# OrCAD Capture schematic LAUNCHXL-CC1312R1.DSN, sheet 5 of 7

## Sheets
5 4_XDS110: size A3
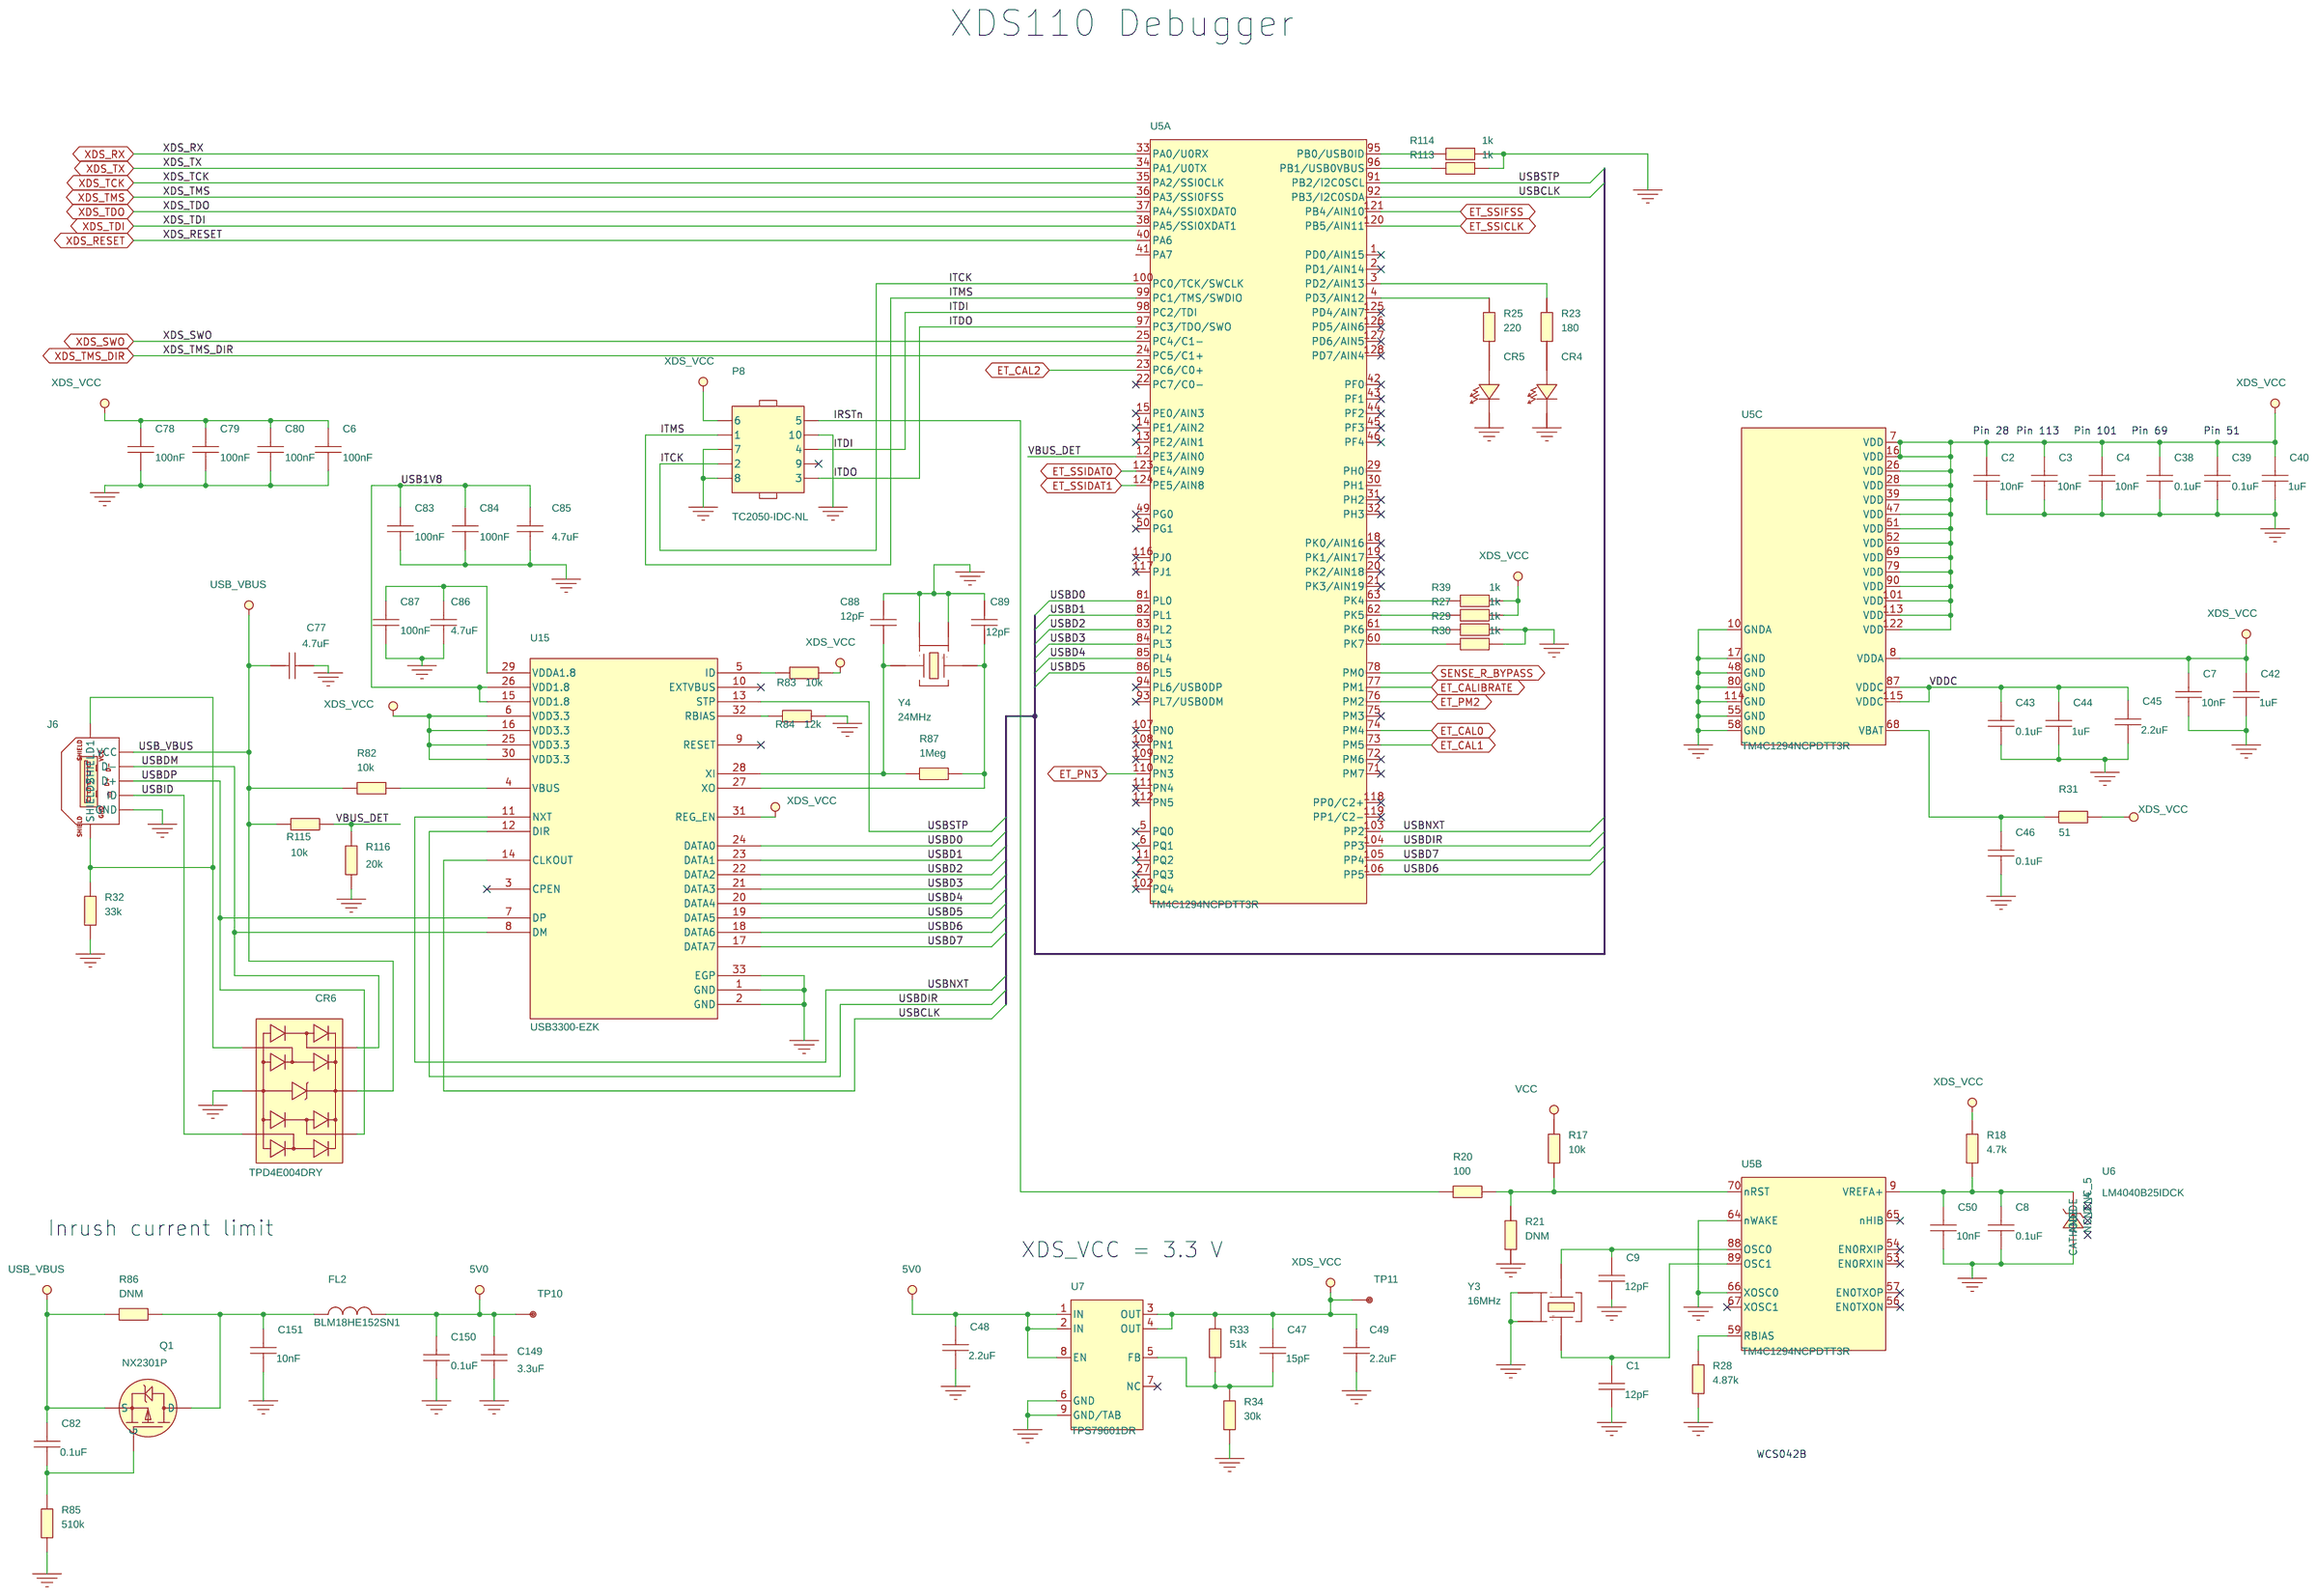
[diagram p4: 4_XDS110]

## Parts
C1  12pF  [CAPC1005X60B2N]
C2  10nF  [CAPC1005X60B2N]
C3  10nF  [CAPC1005X60B2N]
C4  10nF  [CAPC1005X60B2N]
C6  100nF  [CAPC0603X35A2N]
C7  10nF  [CAPC1005X60B2N]
C8  0.1uF  [CAPC1005X60B2N]
C9  12pF  [CAPC1005X60B2N]
C38  0.1uF  [CAPC1005X60B2N]
C39  0.1uF  [CAPC1005X60B2N]
C40  1uF  [CAPC1005X60B2N]
C42  1uF  [CAPC1005X60B2N]
C43  0.1uF  [CAPC1005X60B2N]
C44  1uF  [CAPC1005X60B2N]
C45  2.2uF  [CAPC1005X60B2N]
C46  0.1uF  [CAPC1005X60B2N]
C47  15pF  [CAPC1005X60B2N]
C48  2.2uF  [CAPC1005X60B2N]
C49  2.2uF  [CAPC1005X60B2N]
C50  10nF  [CAPC1005X60B2N]
C77  4.7uF  [CAPC2012X150A2N]
C78  100nF  [CAPC0603X35A2N]
C79  100nF  [CAPC0603X35A2N]
C80  100nF  [CAPC0603X35A2N]
C82  0.1uF  [CAPC1005X60B2N]
C83  100nF  [CAPC0603X35N]
C84  100nF  [CAPC0603X35N]
C85  4.7uF  [CAPC1005X60B2N]
C86  4.7uF  [CAPC1005X60B2N]
C87  100nF  [CAPC0603X35N]
C88  12pF  [CAPC1005X60B2N]
C89  12pF  [CAPC1005X60B2N]
C149  3.3uF  [CAPC1608X90A2N]
C150  0.1uF  [CAPC1005X60B2N]
C151  10nF  [CAPC1005X60B2N]
CR4  LS L296-P2Q2-1  [LEDC1708X67L]
CR5  LPL296-J2L2-25  [LEDC1707X65L]
CR6  TPD4E004DRY  [SON50P100X145X60-6N]
FL2  BLM18HE152SN1  [FIL_BLM18HE152SN1DL]
J6  105164-0001  [MOLEX_1051640001_A2N]
P8  TC2050-IDC-NL  [TAGCONNECT_TC2050IDCNL_A2N]
Q1  NX2301P  [SOT95P230X110-3N]
R17  10k  [RESC1005X40B2N]
R18  4.7k  [RESC1005X40B2N]
R20  100  [RESC1005X40B2N]
R21  DNM  [RESC1005X40B2N]
R23  180  [RESC1005X40B2N]
R25  220  [RESC1005X40B2N]
R27  1k  [RESC1005X40B2N]
R28  4.87k  [RESC1005X40B2N]
R29  1k  [RESC1005X40B2N]
R30  1k  [RESC1005X40B2N]
R31  51  [RESC1005X40B2N]
R32  33k  [RESC1005X40B2N]
R33  51k  [RESC1005X40B2N]
R34  30k  [RESC1005X40B2N]
R39  1k  [RESC1005X40B2N]
R82  10k  [RESC0603X35N]
R83  10k  [RESC0603X35N]
R84  12k  [RESC0603X35N]
R85  510k  [RESC1005X40N]
R86  DNM  [RESC1005X40B2N]
R87  1Meg  [RESC1005X40B2N]
R113  1k  [RESC0603X35N]
R114  1k  [RESC0603X35N]
R115  10k  [RESC0603X35N]
R116  20k  [RESC0603X35N]
TP10  HOLE_0.6mm_PTH  [MTG60_120]
TP11  HOLE_0.6mm_PTH  [MTG60_120]
U5  TM4C1294NCPDTT3R  [QFP40P1600X1600X120-128N]  (sections A,B,C)
U6  LM4040B25IDCK  [SOT65P210X110-5N]
U7  TPS79601DR  [SON65P300X300X100-9AL]
U15  USB3300-EZK  [QFNWB50P500X500X100-33N]
Y3  16MHz  [OSCCC250X320X100-4BN]
Y4  24MHz  [OSCCC250X320X70-4AN]

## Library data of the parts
C1 C9 C88 C89 = CAPACITOR: CAPACITOR, CERAMIC C0G/NP0, 12pF, 50V, -5%/+5%, -55DEGC/+125DEGC, 0402, SMD; AutoDoc File: https://notefied-dynamic-precision.com/DB/Apps/Desktop/Item/Object.aspx?id=113345; BU Name: TEXAS INSTRUMENTS NORWAY; Budget Currency: EUR; Budget Price: 0.007; Country of Origin: PHILIPPINES; Datasheet URL 1: http://psearch.murata.com/capacitor/product/GRM1555C1H120JA01%23.pdf; Datasheet URL 2: http://search.murata.co.jp/Ceramy/image/img/w_hinm/L0005E.pdf; Definied Quality: INDUSTRIAL; Dielectric Type: C0G/NP0; Esd Level: N/A; Last Time Buy: N/A; Lead Time: 12; LifeCycle Status: ACTIVE; MPN: CAPACITOR_0402_12pF_C0G/NP0_M_+/-5%_50V; MPN Status: ACTIVE; MSL: N/A; MTBF: N/A; MTBF Standard: N/A; Manufacturer: MANUFACTURER SELECTION; Max Oper Temp: +125DEGC; Max Tol: +5%; Min Oper Temp: -55DEGC; Min Tol: -5%; Mounting Type: SMD; NOTE Status: PREFERRED; Old Footprint: CAPC1005X60N; PCB Package: 0402; Packing Size: 10000; Packing Type: TAPE_&_REEL; Part Number: 02-07617; Part Type: CAPACITOR\CERAMIC\0402\STANDARD; REACH/SVHC_COMPLIANCE: COMPLIANT; REACH/SVHC_DETAILS: SVHC LIST VERSION Dec 17, 2015; REACH/SVHC_SOURCE: REACH DECLARATION; REACH/SVHC_STATUS: UNAFFECTED; Revision: R000; RoHS Status: ROHS_COMPLIANT; Rtd Voltage: 50V; Vendor: MURATA; Vendor Part Number: GRM1555C1H120JA01D; Vendor Part Status: ACTIVE; WEIGHT: 0.0016g
C2-C4 C7 C50 C151 = CAPACITOR: CAPACITOR, CERAMIC X7R, 10nF, 25V, -10%/+10%, -55DEGC/+125DEGC, 0402, SMD; AutoDoc File: https://notefied-dynamic-precision.com/DB/Apps/Desktop/Item/Object.aspx?id=114570; BU Name: TEXAS INSTRUMENTS NORWAY; Budget Currency: EUR; Budget Price: 0.003; Client Status: UNDER_REVIEW; Country of Origin: JAPAN,CHINA; Datasheet URL 1: http://psearch.murata.com/capacitor/product/GRM155R71E103KA01%23.pdf; Datasheet URL 2: http://search.murata.co.jp/Ceramy/image/img/w_hinm/L0005E.pdf; Definied Quality: INDUSTRIAL; Dielectric Type: X7R; Esd Level: N/A; Last Time Buy: N/A; Lead Time: 18; LifeCycle Status: ACTIVE; MPN: CAPACITOR_0402_10nF_X7R_M_+/-10%_25V; MPN Status: ACTIVE; MSL: N/A; MTBF: N/A; MTBF Standard: N/A; Manufacturer: MANUFACTURER SELECTION; Max Oper Temp: +125DEGC; Max Tol: +10%; Min Oper Temp: -55DEGC; Min Tol: -10%; Mounting Type: SMD; NOTE Status: PREFERRED; Old Footprint: CAPC1005X60N; PCB Package: 0402; Packing Size: 10000; Packing Type: TAPE_&_REEL; Part Number: 02-07775; Part Type: CAPACITOR\CERAMIC\0402\STANDARD; REACH/SVHC_COMPLIANCE: COMPLIANT; REACH/SVHC_DETAILS: SVHC LIST VERSION Dec 17, 2015; REACH/SVHC_SOURCE: MATERIAL DECLARATION; REACH/SVHC_STATUS: UNAFFECTED; Revision: R000; RoHS Status: ROHS_COMPLIANT; Rtd Voltage: 25V; Vendor: MURATA; Vendor Part Number: GRM155R71E103KA01D; Vendor Part Status: ACTIVE; WEIGHT: 0.0016g
C6 C78-C80 = CAPACITOR: CAPACITOR, CERAMIC X5R, 100nF, 10V, -10%/+10%, -55DEGC/+85DEGC, 0201, SMD; ALT_SYMBOLS: CAPC0603X35A2L,CAPC0603X35A2M; AutoDoc File: https://notefied-dynamic-precision.com/DB/Apps/Desktop/Item/Object.aspx?id=96679; BU Name: DYNAMIC PRECISION GDANSK; Budget Currency: EUR; Budget Price: 0.008; Client Status: UNDER_REVIEW; Country of Origin: MISSING INFO; Datasheet URL 1: http://psearch.murata.com/capacitor/product/GRM033R61A104KE84%23.pdf; Datasheet URL 2: http://search.murata.co.jp/Ceramy/image/img/w_hinm/L0005E.pdf; Dielectric Type: X5R; Last Time Buy: N/A; Lead Time: 17; LifeCycle Status: ACTIVE; MPN: GRM155R70J104KA01D; MPN Status: ACTIVE; Manufacturer: MURATA; Max Oper Temp: +85DEGC; Max Tol: +10%; Min Oper Temp: -55DEGC; Min Tol: -10%; Mounting Type: SMD; NOTE Status: PREFERRED; Old Footprint: CAPC1005X60N,0402; PCB Package: 0201; Packing Size: 15000; Packing Type: TAPE_&_REEL; Part Number: 02-06085; Part Type: CAPACITOR\CERAMIC\0201\STANDARD; REACH/SVHC_COMPLIANCE: COMPLIANT; REACH/SVHC_DETAILS: SVHC LIST VERSION Jun 20, 2016; REACH/SVHC_SOURCE: REACH DECLARATION; REACH/SVHC_STATUS: UNAFFECTED; Revision: R004; RoHS Status: ROHS_COMPLIANT; Rtd Voltage: 10V; Vendor: MURATA; Vendor Part Number: GRM033R61A104KE84D; Vendor Part Status: ACTIVE; WEIGHT: 0.00033g
C8 C38 C39 C43 C46 C150 = CAPACITOR: CAPACITOR, CERAMIC X7R, 0.1uF, 25V, -10%/+10%, -55DEGC/+125DEGC, 0402, SMD; AutoDoc File: https://notefied-dynamic-precision.com/DB/Apps/Desktop/Item/Object.aspx?id=115293; BU Name: TEXAS INSTRUMENTS NORWAY; Client Status: UNDER_REVIEW; Datasheet URL 1: http://psearch.en.murata.com/capacitor/product/GRM155R71E104KE14%23.pdf; Datasheet URL 2: http://search.murata.co.jp/Ceramy/image/img/w_hinm/L0005E.pdf; Dielectric Type: X7R; Last Time Buy: N/A; LifeCycle Status: ACTIVE; MPN: GRM155R70J104KA01D; MPN Status: ACTIVE; Manufacturer: MURATA; Max Oper Temp: +125DEGC; Max Tol: +10%; Min Oper Temp: -55DEGC; Min Tol: -10%; Mounting Type: SMD; NOTE Status: PREFERRED; Old Footprint: CAPC1005X60N,0402; PCB Package: 0402; Packing Size: 10000; Packing Type: TAPE_&_REEL; Part Number: 02-07861; Part Type: CAPACITOR\CERAMIC\0402\STANDARD; REACH/SVHC_COMPLIANCE: COMPLIANT; REACH/SVHC_DETAILS: SVHC LIST VERSION Jun 20, 2016; REACH/SVHC_SOURCE: REACH DECLARATION; REACH/SVHC_STATUS: UNAFFECTED; Revision: R002; RoHS Status: ROHS_COMPLIANT; Rtd Voltage: 25V; Vendor: MURATA; Vendor Part Number: GRM155R71E104KE14D; Vendor Part Status: ACTIVE; WEIGHT: 0.0016g
C40 C42 C44 = CAPACITOR: CAPACITOR, CERAMIC X5R, 1uF, 16V, -10%/+10%, -55DEGC/+85DEGC, 0402, SMD; AutoDoc File: https://notefied-dynamic-precision.com/DB/Apps/Desktop/Item/Object.aspx?id=115295; BU Name: TEXAS INSTRUMENTS NORWAY; Client Status: UNDER_REVIEW; Datasheet URL 1: http://psearch.en.murata.com/capacitor/product/GRM155R61C105KA12%23.pdf; Datasheet URL 2: http://search.murata.co.jp/Ceramy/image/img/w_hinm/L0005E.pdf; Definied Quality: INDUSTRIAL; Dielectric Type: X5R; Esd Level: N/A; Last Time Buy: N/A; MPN: GRM155R61A105KE15D; MPN Status: ACTIVE; MSL: 1; MTBF: N/A; MTBF Standard: N/A; Manufacturer: MURATA; Max Oper Temp: +85DEGC; Max Tol: +10%; Min Oper Temp: -55DEGC; Min Tol: -10%; Mounting Type: SMD; NOTE Status: PREFERRED; Old Footprint: CAPC1005X60N,0402; PCB Package: 0402; Packing Size: 10000; Packing Type: TAPE_&_REEL; Part Number: 02-07863; Part Type: CAPACITOR\CERAMIC\0402\STANDARD; REACH/SVHC_COMPLIANCE: COMPLIANT; REACH/SVHC_DETAILS: SVHC LIST VERSION Jun 20, 2016; REACH/SVHC_SOURCE: REACH DECLARATION; REACH/SVHC_STATUS: UNAFFECTED; Revision: R002; RoHS Status: ROHS_COMPLIANT; Rtd Voltage: 16V; Vendor: MURATA; Vendor Part Number: GRM155R61C105KA12D; Vendor Part Status: ACTIVE; WEIGHT: 0.0016g
C45 C48 C49 = CAPACITOR: CAPACITOR, CERAMIC X5R, 2.2uF, 6.3V, -10%/+10%, -55DEGC/+85DEGC, 0402, SMD; AutoDoc File: https://notefied-dynamic-precision.com/DB/Apps/Desktop/Item/Object.aspx?id=113352; BU Name: TEXAS INSTRUMENTS NORWAY; Budget Currency: USD; Budget Price: 0.0126; Country of Origin: PHILIPPINES; Datasheet URL 1: http://psearch.murata.com/capacitor/product/GRM155R60J225KE95%23.pdf; Datasheet URL 2: http://psearch.en.murata.com/capacitor/product/GRM155R60J225KE95%23.html; Dielectric Type: X5R; Last Time Buy: N/A; Lead Time: N/A; Max Oper Temp: +85DEGC; Max Tol: +10%; Min Oper Temp: -55DEGC; Min Tol: -10%; Mounting Type: SMD; PCB Package: 0402; Packing Size: 10000; Packing Type: TAPE_&_REEL; Part Number: 02-07624; Part Type: CAPACITOR\CERAMIC\0402\STANDARD; Revision: R000; RoHS Status: ROHS_COMPLIANT; Rtd Voltage: 6.3V; Vendor: MURATA; Vendor Part Number: GRM155R60J225KE95D; Vendor Part Status: NRND; Weight: 0.0016g
C47 = CAPACITOR: CAPACITOR, CERAMIC C0G/NP0, 15pF, 50V, -5%/+5%, -55DEGC/+125DEGC, 0402, SMD; AutoDoc File: https://notefied-dynamic-precision.com/DB/Apps/Desktop/Item/Object.aspx?id=114571; BU Name: TEXAS INSTRUMENTS NORWAY; Budget Currency: EUR; Budget Price: 0.006; Client Status: UNDER_REVIEW; Country of Origin: PHILIPPINES; Datasheet URL 1: http://psearch.murata.com/capacitor/product/GRM1555C1H150JA01%23.pdf; Datasheet URL 2: http://search.murata.co.jp/Ceramy/image/img/w_hinm/L0005E.pdf; Definied Quality: INDUSTRIAL; Dielectric Type: C0G/NP0; Esd Level: N/A; Last Time Buy: N/A; Lead Time: 12; LifeCycle Status: ACTIVE; MPN: CAPACITOR_0402_15pF_C0G/NP0_M_+/-5%_50V; MPN Status: ACTIVE; MSL: N/A; MTBF: N/A; MTBF Standard: N/A; Manufacturer: MANUFACTURER SELECTION; Max Oper Temp: +125DEGC; Max Tol: +5%; Min Oper Temp: -55DEGC; Min Tol: -5%; Mounting Type: SMD; NOTE Status: PREFERRED; Old Footprint: CAPC1005X60N; PCB Package: 0402; Packing Size: 10000; Packing Type: TAPE_&_REEL; Part Number: 02-07776; Part Type: CAPACITOR\CERAMIC\0402\STANDARD; REACH/SVHC_COMPLIANCE: COMPLIANT; REACH/SVHC_DETAILS: SVHC LIST VERSION Dec 17, 2015; REACH/SVHC_SOURCE: REACH DECLARATION; REACH/SVHC_STATUS: UNAFFECTED; Revision: R000; RoHS Status: ROHS_COMPLIANT; Rtd Voltage: 50V; Vendor: MURATA; Vendor Part Number: GRM1555C1H150JA01D; Vendor Part Status: ACTIVE; WEIGHT: 0.0016g
C77 = CAPACITOR: CAPACITOR, CERAMIC X7R, 4.7uF, 25V, -10%/+10%, -55DEGC/+125DEGC, 0805, SMD; ALT_SYMBOLS: CAPC2012X150A2L,CAPC2012X150A2M; AutoDoc File: https://notefied-dynamic-precision.com/DB/Apps/Desktop/Item/Object.aspx?id=100426; BU Name: DYNAMIC PRECISION GDANSK; Budget Currency: EUR; Budget Price: 0.165; Client Status: UNDER_REVIEW; Country of Origin: JAPAN,CHINA; Datasheet URL 1: http://product.tdk.com/info/en/documents/chara_sheet/C2012X7R1E475K125AB.pdf; Datasheet URL 2: http://product.tdk.com/info/en/catalog/datasheets/mlcc_commercial_general_en.pdf; Dielectric Type: X7R; Last Time Buy: N/A; Lead Time: 14; Max Oper Temp: +125DEGC; Max Tol: +10%; Min Oper Temp: -55DEGC; Min Tol: -10%; Mounting Type: SMD; PCB Package: 0805; Packing Size: 2000; Packing Type: TAPE_&_REEL; Part Number: 02-06852; Part Type: CAPACITOR\CERAMIC\0805\STANDARD; Revision: R001; RoHS Status: ROHS_COMPLIANT; Rtd Voltage: 25V; Vendor: TDK; Vendor Part Number: C2012X7R1E475K125AB; Vendor Part Status: ACTIVE; Weight: 0.01563g
C82 = CAPACITOR: CAPACITOR, CERAMIC X7R, 0.1uF, 25V, -10%/+10%, -55DEGC/+125DEGC, 0402, SMD; AutoDoc File: https://notefied-dynamic-precision.com/DB/Apps/Desktop/Item/Object.aspx?id=115293; BU Name: TEXAS INSTRUMENTS NORWAY; Client Status: UNDER_REVIEW; Datasheet URL 1: http://psearch.en.murata.com/capacitor/product/GRM155R71E104KE14%23.pdf; Datasheet URL 2: http://search.murata.co.jp/Ceramy/image/img/w_hinm/L0005E.pdf; Dielectric Type: X7R; Last Time Buy: N/A; Max Oper Temp: +125DEGC; Max Tol: +10%; Min Oper Temp: -55DEGC; Min Tol: -10%; Mounting Type: SMD; PCB Package: 0402; Packing Size: 10000; Packing Type: TAPE_&_REEL; Part Number: 02-07861; Part Type: CAPACITOR\CERAMIC\0402\STANDARD; REACH/SVHC_COMPLIANCE: COMPLIANT; REACH/SVHC_DETAILS: SVHC LIST VERSION Jun 20, 2016; REACH/SVHC_SOURCE: REACH DECLARATION; REACH/SVHC_STATUS: UNAFFECTED; Revision: R002; RoHS Status: ROHS_COMPLIANT; Rtd Voltage: 25V; Vendor: MURATA; Vendor Part Number: GRM155R71E104KE14D; Vendor Part Status: ACTIVE; Weight: 0.0016g
C83 C84 C87 = CAPACITOR: CAPACITOR, CERAMIC X5R, 100nF, 10V, -10%/+10%, -55DEGC/+85DEGC, 0201, SMD; ALT_SYMBOLS: CAPC0603X35L,CAPC0603X35M; AutoDoc File: https://notefied-dynamic-precision.com/DB/Apps/Desktop/Item/Object.aspx?id=96679; BU Name: DYNAMIC PRECISION GDANSK; Budget Currency: EUR; Budget Price: 0.008; Client Status: UNDER_REVIEW; Country of Origin: MISSING INFO; Datasheet URL 1: http://psearch.murata.com/capacitor/product/GRM033R61A104KE84%23.pdf; Datasheet URL 2: N/A; Dielectric Type: X5R; Last Time Buy: N/A; Lead Time: 17; LifeCycle Status: ACTIVE; MPN: GRM155R70J104KA01D; MPN Status: ACTIVE; Manufacturer: MURATA; Max Oper Temp: +85DEGC; Max Tol: +10%; Min Oper Temp: -55DEGC; Min Tol: -10%; Mounting Type: SMD; NOTE Status: PREFERRED; Old Footprint: CAPC1005X60N,0402; PCB Package: 0201; Packing Size: 15000; Packing Type: TAPE_&_REEL; Part Number: 02-06085; Part Type: CAPACITOR\CERAMIC\0201\STANDARD; REACH/SVHC_COMPLIANCE: COMPLIANT; REACH/SVHC_DETAILS: SVHC LIST VERSION Dec 17, 2015; REACH/SVHC_SOURCE: REACH DECLARATION; REACH/SVHC_STATUS: UNAFFECTED; Revision: R002; RoHS Status: ROHS_COMPLIANT; Rtd Voltage: 10V; Vendor: MURATA; Vendor Part Number: GRM033R61A104KE84D; Vendor Part Status: ACTIVE; WEIGHT: 0.00033g
C85 C86 = CAPACITOR: CAPACITOR, CERAMIC X5R, 4.7uF, 6.3V, -20%/+20%, -55DEGC/+85DEGC, 0402, SMD; AutoDoc File: https://notefied-dynamic-precision.com/DB/Apps/Desktop/Item/Object.aspx?id=113357; BU Name: TEXAS INSTRUMENTS NORWAY; Budget Currency: USD; Budget Price: 0.03; Country of Origin: PHILIPPINES; Datasheet URL 1: http://psearch.murata.com/capacitor/product/GRM155R60J475ME87%23.pdf; Datasheet URL 2: http://search.murata.co.jp/Ceramy/image/img/w_hinm/L0005E.pdf; Dielectric Type: X5R; Last Time Buy: N/A; Lead Time: 14; Max Oper Temp: +85DEGC; Max Tol: +20%; Min Oper Temp: -55DEGC; Min Tol: -20%; Mounting Type: SMD; PCB Package: 0402; Packing Size: 10000; Packing Type: TAPE_&_REEL; Part Number: 02-07629; Part Type: CAPACITOR\CERAMIC\0402\STANDARD; REACH/SVHC_COMPLIANCE: COMPLIANT; REACH/SVHC_DETAILS: SVHC LIST VERSION Dec 17, 2015; REACH/SVHC_SOURCE: REACH DECLARATION; REACH/SVHC_STATUS: UNAFFECTED; Revision: R000; RoHS Status: ROHS_COMPLIANT; Rtd Voltage: 6.3V; Vendor: MURATA; Vendor Part Number: GRM155R60J475ME87D; Vendor Part Status: NRND; Weight: 0.0025g
C149 = CAPACITOR: CAPACITOR, CERAMIC X5R, 3.3uF, 10V, -10%/+10%, -55DEGC/+85DEGC, 0603, SMD; ALT_SYMBOLS: CAPC1608X90A2L,CAPC1608X90A2M; AutoDoc File: https://notefied-dynamic-precision.com/DB/Apps/Desktop/Item/Object.aspx?id=94637; BU Name: DYNAMIC PRECISION GDANSK; Budget Currency: EUR; Budget Price: 0.06; Client Status: UNDER_REVIEW; Country of Origin: PHILIPPINES; Datasheet URL 1: http://psearch.murata.com/capacitor/product/GRM188R61A335KE15%23.pdf; Datasheet URL 2: http://search.murata.co.jp/Ceramy/image/img/w_hinm/L0005E.pdf; Dielectric Type: X5R; Last Time Buy: N/A; Lead Time: 20; Max Oper Temp: +85DEGC; Max Tol: +10%; Min Oper Temp: -55DEGC; Min Tol: -10%; Mounting Type: SMD; PCB Package: 0603; Packing Size: 4000; Packing Type: TAPE_&_REEL; Part Number: 02-05897; Part Type: CAPACITOR\CERAMIC\0603\STANDARD; Revision: R001; RoHS Status: ROHS_COMPLIANT; Rtd Voltage: 10V; Vendor: MURATA; Vendor Part Number: GRM188R61A335KE15D; Vendor Part Status: NRND; Weight: 0.0063g
CR4 = LED_0: OPTO, LED, SUPER RED COLOR, 630nm, 1.8V TO 2.3V, 0.06A, 0603, SMD; ALT_SYMBOLS: LEDC1708X67L,LEDC1708X67M; AutoDoc File: http://notefied-dynamic-precision.com/DB/Apps/Desktop/Item/Object.aspx?id=88355; Budget Currency: USD; Budget Price: 0.089; Datasheet URL 1: http://www.osram-os.com/osram_os/en/products/product-catalog/led-light-emitting-diodes/smartled-0603/ls-l296/index.jsp?search_result=%2fosram_os%2fen%2fsearch%2fadvanced_search.jsp%3faction%3ddosearch%26inp_searchterm_1%3dLS%2bL296-P2Q2-1%26website_name%3; Datasheet URL 2: http://www.osram-os.com/Graphics/XPic5/00077119_0.pdf/LS%20L296%20-%20SMARTLED%200603.pdf; Definied Quality: INDUSTRIAL; Esd Level: HBM 2kV; FPLIST: LEDC1708X67N,LEDC1708X67L,LEDC1708X67M; Last Time Buy: N/A; Lead Time: 8; MPN Status: NRND; MSL: 2; MTBF: N/A; MTBF Standard: N/A; Manufacturer: OSRAM; Max Oper Temp: +100DEGC; Min Oper Temp: -40DEGC; Mounting Type: SMD; NOTE Status: PREFERRED; Old Footprint: LEDC1708X67N; PCB Package: 0603; PPCB Recomendation: Inactive for new design [Alert:0001]; Packing Size: 5000; Packing Type: TAPE_&_REEL; Part Number: 15-01169; Part Type: OPTO\LED\0603; Revision: R003; RoHS Status: ROHS_COMPLIANT; Rtd Current: 0.06A; Rtd Voltage: 1.8V TO 2.3V; WEIGHT: 0.002g
CR5 = LED_0: OPTO, LED, GREEN COLOR, 562nm, 0.02A, 0.08W, 0603, SMD; ALT_SYMBOLS: LEDC1707X65L,LEDC1707X65M; AutoDoc File: http://notefied-dynamic-precision.com/DB/Apps/Desktop/Item/Object.aspx?id=81622; Budget Currency: USD; Budget Price: 0.1263; Datasheet URL 1: N/A; Datasheet URL 2: http://catalog.osram-os.com/jsp/download.jsp?rootPath=/media/&name=LP_L296.pdf&docPath=Graphics/00077128_0.pdf&url=/media//_en/Graphics/00077128_0.pdf; Definied Quality: INDUSTRIAL; Esd Level: HBM 2kV; FPLIST: LEDC1707X65N,LEDC1707X65L,LEDC1707X65M; Last Time Buy: N/A; Lead Time: 8; MPN: LP L296-J2L2-25; MPN Status: NRND; MSL: 2; MTBF: N/A; MTBF Standard: N/A; Manufacturer: OSRAM; Max Oper Temp: +100DEGC; Min Oper Temp: -40DEGC; Mounting Type: SMD; NOTE Status: NOT_PREFERRED; Old Footprint: LEDC1707X65N; PCB Package: 0603; Packing Size: 5000; Packing Type: TAPE_&_REEL; Part Number: 15-01023; Part Type: OPTO\LED\0603; Revision: R003; RoHS Status: ROHS_COMPLIANT; Rtd Current: 0.02A; Rtd Power: 0.08W; Rtd Voltage: 2V; WEIGHT: 0.002g
CR6 = DIODE_TPD4E004_SON6: DIODE, PROTECTION, ESD ARRAY, 4 CHANNEL, 6V TO 8V, -40DEGC/+85DEGC, SON6, SMD; ALT_SYMBOLS: SON50P100X145X65-6L,SON50P100X145X65-6M; AutoDoc File: http://notefied-dynamic-precision.com/DB/Apps/Desktop/Item/Object.aspx?id=96191; Budget Currency: USD; Budget Price: 0.22; Datasheet URL 1: http://www.ti.com/lit/ml/mpds221e/mpds221e.pdf; Datasheet URL 2: http://www.ti.com/lit/ds/symlink/tpd4e004.pdf; Definied Quality: INDUSTRIAL; Esd Level: HBM 15kV; FPLIST: SON50P100X145X60-6N,SON50P100X145X65-6N,SON50P100X145X65-6L,SON50P100X145X65-6M; Last Time Buy: N/A; Lead Time: 10; MPN: TPD4E004DRYR; MPN Status: ACTIVE; MSL: 1; MTBF: 9.90*10^8; MTBF Standard: CL=60%,Ta=55degC,Tt=125degC,Ea=0.7eV; Manufacturer: TEXAS INSTRUMENTS; Max Oper Temp: +85DEGC; Min Oper Temp: -40DEGC; Mounting Type: SMD; NOTE Status: PREFERRED; Old Footprint: SON50P100X145X60-6N,SON50P100X145X65-6N; PCB Package: SON6; Packing Size: 5000; Packing Type: TAPE_&_REEL; Part Number: 14-06172; Part Type: DIODE\PROTECTION; Revision: R002; RoHS Status: ROHS_COMPLIANT; Rtd Voltage: 6V TO 8V; WEIGHT: 0.0028462g
FL2 = FILTER_2PIN: FILTER, EMI, 1500@100MHz, -55DEGC/+125DEGC, 0603, SMD; ALT_SYMBOLS: FIL_BLM18HE152SN1DL,FIL_BLM18HE152SN1DM; AutoDoc File: http://notefied-dynamic-precision.com/DB/Apps/Desktop/Item/Object.aspx?id=85575; Budget Currency: EUR; Budget Price: 0.085; Datasheet URL 1: http://search.murata.co.jp/Ceramy/image/img/PDF/ENG/L0110S0101BLM18H.pdf; Datasheet URL 2: http://search.murata.co.jp/Ceramy/image/img/PDF/ENG/L0110S0101BLM18H.pdf; FPLIST: FIL_BLM18HE152SN1DN,FIL_BLM18HE152SN1DL,FIL_BLM18HE152SN1DM; Impedance: 1500@100MHz; Lead Time: 26; MPN: BLM18HE152SN1D; MPN Status: ACTIVE; Manufacturer: MURATA; Max Oper Temp: +125DEGC; Max Tol: +25%; Min Oper Temp: -55DEGC; Min Tol: -25%; Mounting Type: SMD; NOTE Status: PREFERRED; Old Footprint: FIL_BLM18HE152SN1DN; PCB Package: 0603; Packing Size: 4000; Packing Type: TAPE_&_REEL; Part Number: 04-00470; Part Type: FILTER\EMI\0603; Revision: R001; RoHS Status: ROHS_COMPLIANT; Rtd Current: 0.5A; WEIGHT: 0.006g
J6 = CONN_USB_MICRO_B_2MH: CONNECTOR, USB, FEMALE, RIGHT ANGLE, 1 ROW, 5 PINS, PITCH 0.65mm, SMD; ALT_SYMBOLS: MOLEX_1051640001_A2L,MOLEX_1051640001_A2M; AutoDoc File: http://notefied-dynamic-precision.com/DB/Apps/Desktop/Item/Object.aspx?id=104390; Datasheet URL 1: http://www.molex.com/pdm_docs/sd/1051640001_sd.pdf; Datasheet URL 2: http://www.molex.com/webdocs/datasheets/pdf/en-us/1051640001_IO_CONNECTORS.pdf; FPLIST: MOLEX_1051640001_A2N,MOLEX_1051640001_A2L,MOLEX_1051640001_A2M; MPN Status: ACTIVE; Manufacturer: MOLEX; Max Oper Temp: +85DEGC; Min Oper Temp: -30DEGC; Mounting Type: SMD; NOTE Status: PREFERRED; No Of Pos: 5; No Of Rows: 1; Packing Type: TAPE_&_REEL; Part Number: 06-04998; Part Type: CONNECTOR\USB\MICRO_USB-B; Pitch: 0.65mm; Revision: R001; RoHS Status: ROHS_COMPLIANT; Rtd Current: 1.8V; Rtd Voltage: 30V; WEIGHT: 0.234g
P8 = CONN_IDC_TC2050-IDC-NL: NON COMPONENT, CONNECTOR, CABLE, PLUG OF NAILS, 10 PINS, 2 ROWS, SMD; ALT_SYMBOLS: TAGCONNECT_TC2050IDCNL_A2L,TAGCONNECT_TC2050IDCNL_A2M; AutoDoc File: https://notefied-dynamic-precision.com/DB/Apps/Desktop/Item/Object.aspx?id=96644; BU Name: DYNAMIC PRECISION GDANSK; Old Footprint: TAGCONNECT_TC2050IDCNLN; Part Number: 19-00452; Part Type: NON_COMPONENT\CONNECTOR; Revision: R002
Q1 = MOSFET_P_NX2301P_SOT23-3: TRANSISTOR, MOSFET, P-CHANNEL, -20V, -2A, 0.4W, SOT23-3, SMD; ALT_SYMBOLS: SOT95P230X110-3L,SOT95P230X110-3M; AutoDoc File: https://notefied-dynamic-precision.com/DB/Apps/Desktop/Item/Object.aspx?id=96676; BU Name: DYNAMIC PRECISION GDANSK; Budget Currency: EUR; Budget Price: 0.075; Client Status: UNDER_REVIEW; Country of Origin: CHINA; Datasheet URL 1: http://cache.nxp.com/documents/data_sheet/NX2301P.pdf?pspll=1; Datasheet URL 2: http://www.nxp.com/documents/outline_drawing/SOT23.pdf; Last Time Buy: N/A; Lead Time: 3; Max Oper Temp: +150DEGC; Min Oper Temp: -55DEGC; Mounting Type: SMD; PCB Package: SOT23-3; Packing Size: 3000; Packing Type: TAPE_&_REEL; Part Number: 16-04969; Part Type: TRANSISTOR\UNIPOLAR\FET\MOSFET\P-CHANNEL; Revision: R001; RoHS Status: ROHS_COMPLIANT; Rtd Current: -2A; Rtd Power: 0.4W; Rtd Voltage: -20V; Vendor: NXP; Vendor Part Number: NX2301P,215; Vendor Part Status: ACTIVE; Weight: 0.00763g
R17 = RESISTOR: RESISTOR, THICK FILM, 10k, -5%/+5%, 0.063W, 50V, -55DEGC/+155DEGC, 0402, SMD; AutoDoc File: https://notefied-dynamic-precision.com/DB/Apps/Desktop/Item/Object.aspx?id=113326; BU Name: TEXAS INSTRUMENTS NORWAY; Budget Currency: EUR; Budget Price: 0.014; Client Status: UNDER_REVIEW; Country of Origin: ISRAEL; Datasheet URL 1: http://www.vishay.com/docs/20035/dcrcwe3.pdf; Datasheet URL 2: N/A; Definied Quality: INDUSTRIAL; Esd Level: N/A; Last Time Buy: N/A; Lead Time: 18; LifeCycle Status: ACTIVE; MPN: RESISTOR_0402_10k_+/-5%_50V_0.063W_M_+/-200ppm; MPN Status: ACTIVE; MSL: N/A; MTBF: N/A; MTBF Standard: N/A; Manufacturer: MANUFACTURER SELECTION; Max Oper Temp: +155DEGC; Max TC: +200PPM/DEGC; Max Tol: +5%; Min Oper Temp: -55DEGC; Min TC: -200PPM/DEGC; Min Tol: -5%; Mounting Type: SMD; NOTE Status: PREFERRED; Old Footprint: RESC1005X40N; PCB Package: 0402; Packing Size: 10000; Packing Type: TAPE_&_REEL; Part Number: 01-22353; Part Type: RESISTOR\0402\STANDARD; REACH/SVHC_COMPLIANCE: COMPLIANT; REACH/SVHC_DETAILS: SVHC LIST VERSION Jun 20, 2016; REACH/SVHC_SOURCE: MATERIAL DECLARATION; REACH/SVHC_STATUS: UNAFFECTED; Resistor Type: THICK FILM; Revision: R001; RoHS Status: ROHS_COMPLIANT_WITH_EXEMPTION; Rtd Current: N/A; Rtd Power: 0.063W; Rtd Voltage: 50V; Vendor: VISHAY; Vendor Part Number: CRCW040210K0JNED; Vendor Part Status: ACTIVE; WEIGHT: 0.00065g
R18 = RESISTOR: RESISTOR, THICK FILM, 4.7k, -5%/+5%, 0.063W, 50V, -55DEGC/+155DEGC, 0402, SMD; AutoDoc File: https://notefied-dynamic-precision.com/DB/Apps/Desktop/Item/Object.aspx?id=114562; BU Name: TEXAS INSTRUMENTS NORWAY; Budget Currency: EUR; Budget Price: 0.014; Client Status: UNDER_REVIEW; Country of Origin: ISRAEL; Datasheet URL 1: http://www.vishay.com/docs/20035/dcrcwe3.pdf; Datasheet URL 2: N/A; Definied Quality: INDUSTRIAL; Esd Level: N/A; Last Time Buy: N/A; Lead Time: 18; LifeCycle Status: ACTIVE; MPN: RESISTOR_0402_4.7k_+/-5%_50V_0.063W_M_+/-200ppm; MPN Status: ACTIVE; MSL: N/A; MTBF: N/A; MTBF Standard: N/A; Manufacturer: MANUFACTURER SELECTION; Max Oper Temp: +155DEGC; Max TC: +200PPM/DEGC; Max Tol: +5%; Min Oper Temp: -55DEGC; Min TC: -200PPM/DEGC; Min Tol: -5%; Mounting Type: SMD; NOTE Status: PREFERRED; Old Footprint: RESC1005X40N; PCB Package: 0402; Packing Size: 10000; Packing Type: TAPE_&_REEL; Part Number: 01-22489; Part Type: RESISTOR\0402\STANDARD; REACH/SVHC_COMPLIANCE: COMPLIANT; REACH/SVHC_DETAILS: SVHC LIST VERSION Jun 20, 2016; REACH/SVHC_SOURCE: MATERIAL DECLARATION; REACH/SVHC_STATUS: UNAFFECTED; Resistor Type: THICK FILM; Revision: R000; RoHS Status: ROHS_COMPLIANT; Rtd Current: N/A; Rtd Power: 0.063W; Rtd Voltage: 50V; Vendor: VISHAY; Vendor Part Number: CRCW04024K70JNED; Vendor Part Status: ACTIVE; WEIGHT: 0.00065g
R20 = RESISTOR: RESISTOR, THICK FILM, 100, -5%/+5%, 0.063W, 50V, -55DEGC/+155DEGC, 0402, SMD; AutoDoc File: https://notefied-dynamic-precision.com/DB/Apps/Desktop/Item/Object.aspx?id=114555; BU Name: TEXAS INSTRUMENTS NORWAY; Budget Currency: USD; Budget Price: 0.0014; Client Status: UNDER_REVIEW; Country of Origin: UNITED STATES; Datasheet URL 1: http://www.vishay.com/docs/20035/dcrcwe3.pdf; Datasheet URL 2: N/A; Definied Quality: INDUSTRIAL; Esd Level: N/A; Last Time Buy: N/A; Lead Time: 16; LifeCycle Status: ACTIVE; MPN: RESISTOR_0402_100_+/-1%_50V_0.063W_M_+/-100ppm; MPN Status: ACTIVE; MSL: N/A; MTBF: N/A; MTBF Standard: N/A; Manufacturer: MANUFACTURER SELECTION; Max Oper Temp: +155DEGC; Max TC: +200PPM/DEGC; Max Tol: +5%; Min Oper Temp: -55DEGC; Min TC: -200PPM/DEGC; Min Tol: -5%; Mounting Type: SMD; NOTE Status: PREFERRED; Old Footprint: RESC1005X40N; PCB Package: 0402; Packing Size: 10000; Packing Type: TAPE_&_REEL; Part Number: 01-22482; Part Type: RESISTOR\0402\STANDARD; REACH/SVHC_COMPLIANCE: COMPLIANT; REACH/SVHC_DETAILS: SVHC LIST VERSION Jun 20, 2016; REACH/SVHC_SOURCE: MATERIAL DECLARATION; REACH/SVHC_STATUS: UNAFFECTED; Resistor Type: THICK FILM; Revision: R000; RoHS Status: ROHS_COMPLIANT; Rtd Current: N/A; Rtd Power: 0.063W; Rtd Voltage: 50V; Vendor: VISHAY; Vendor Part Number: CRCW0402100RJNED; Vendor Part Status: ACTIVE; WEIGHT: 0.00065g
R21 = RESISTOR: RESISTOR, DO NOT MOUNT, 0402, SMD; AutoDoc File: https://notefied-dynamic-precision.com/DB/Apps/Desktop/Item/Object.aspx?id=113312; BU Name: TEXAS INSTRUMENTS NORWAY; Budget Currency: N/A; Budget Price: N/A; Country of Origin: MISSING INFO; Datasheet URL 1: N/A; Datasheet URL 2: N/A; Esd Level: N/A; Last Time Buy: N/A; Lead Time: N/A; LifeCycle Status: ACTIVE; MPN Status: ACTIVE; MSL: N/A; MTBF: N/A; MTBF Standard: N/A; Manufacturer: DO NOT MOUNT; Max Oper Temp: N/A; Max TC: N/A; Max Tol: N/A; Min Oper Temp: N/A; Min TC: N/A; Min Tol: N/A; Mounting Type: SMD; NOTE Status: PREFERRED; Old Footprint: RESC1005X40N,0402; PCB Package: 0402; Packing Size: N/A; Part Number: 01-22339; Part Type: RESISTOR\0402\STANDARD; Resistance: N/A; Resistor Type: THICK FILM; Revision: R000; RoHS Status: MISSING_INFO; Rtd Current: N/A; Rtd Power: N/A; Rtd Voltage: N/A; Vendor: DO NOT MOUNT; Vendor Part Status: ACTIVE; WEIGHT: N/A
R23 = RESISTOR: RESISTOR, THICK FILM, 180, -5%/+5%, 0.063W, 50V, -55DEGC/+155DEGC, 0402, SMD; AutoDoc File: https://notefied-dynamic-precision.com/DB/Apps/Desktop/Item/Object.aspx?id=113318; BU Name: TEXAS INSTRUMENTS NORWAY; Budget Currency: EUR; Budget Price: 0.014; Client Status: UNDER_REVIEW; Country of Origin: MISSING INFO; Datasheet URL 1: http://www.vishay.com/docs/20035/dcrcwe3.pdf; Datasheet URL 2: N/A; Definied Quality: INDUSTRIAL; Esd Level: N/A; Last Time Buy: N/A; Lead Time: 18; LifeCycle Status: ACTIVE; MPN: RESISTOR_0402_180_+/-5%_50V_0.063W_M_+/-200ppm; MPN Status: ACTIVE; MSL: N/A; MTBF: N/A; MTBF Standard: N/A; Manufacturer: MANUFACTURER SELECTION; Max Oper Temp: +155DEGC; Max TC: +200PPM/DEGC; Max Tol: +5%; Min Oper Temp: -55DEGC; Min TC: -200PPM/DEGC; Min Tol: -5%; Mounting Type: SMD; NOTE Status: PREFERRED; Old Footprint: RESC1005X40N; PCB Package: 0402; Packing Size: 10000; Packing Type: TAPE_&_REEL; Part Number: 01-22345; Part Type: RESISTOR\0402\STANDARD; REACH/SVHC_COMPLIANCE: COMPLIANT; REACH/SVHC_DETAILS: SVHC LIST VERSION Jun 20, 2016; REACH/SVHC_SOURCE: MATERIAL DECLARATION; REACH/SVHC_STATUS: UNAFFECTED; Resistor Type: THICK FILM; Revision: R001; RoHS Status: ROHS_COMPLIANT_WITH_EXEMPTION; Rtd Current: N/A; Rtd Power: 0.063W; Rtd Voltage: 50V; Vendor: VISHAY; Vendor Part Number: CRCW0402180RJNED; Vendor Part Status: ACTIVE; WEIGHT: 0.00065g
R25 = RESISTOR: RESISTOR, THICK FILM, 220, -5%/+5%, 0.063W, 50V, -55DEGC/+155DEGC, 0402, SMD; AutoDoc File: https://notefied-dynamic-precision.com/DB/Apps/Desktop/Item/Object.aspx?id=113319; BU Name: TEXAS INSTRUMENTS NORWAY; Budget Currency: EUR; Budget Price: 0.014; Client Status: UNDER_REVIEW; Country of Origin: ISRAEL; Datasheet URL 1: http://www.vishay.com/docs/20035/dcrcwe3.pdf; Datasheet URL 2: N/A; Definied Quality: INDUSTRIAL; Esd Level: N/A; Last Time Buy: N/A; Lead Time: 18; LifeCycle Status: ACTIVE; MPN: RESISTOR_0402_220_+/-5%_50V_0.063W_M_+/-200ppm; MPN Status: ACTIVE; MSL: N/A; MTBF: N/A; MTBF Standard: N/A; Manufacturer: MANUFACTURER SELECTION; Max Oper Temp: +155DEGC; Max TC: +200PPM/DEGC; Max Tol: +5%; Min Oper Temp: -55DEGC; Min TC: -200PPM/DEGC; Min Tol: -5%; Mounting Type: SMD; NOTE Status: PREFERRED; Old Footprint: RESC1005X40N; PCB Package: 0402; Packing Size: 10000; Packing Type: TAPE_&_REEL; Part Number: 01-22346; Part Type: RESISTOR\0402\STANDARD; REACH/SVHC_COMPLIANCE: COMPLIANT; REACH/SVHC_DETAILS: SVHC LIST VERSION Jun 20, 2016; REACH/SVHC_SOURCE: MATERIAL DECLARATION; REACH/SVHC_STATUS: UNAFFECTED; Resistor Type: THICK FILM; Revision: R001; RoHS Status: ROHS_COMPLIANT_WITH_EXEMPTION; Rtd Current: N/A; Rtd Power: 0.063W; Rtd Voltage: 50V; Vendor: VISHAY; Vendor Part Number: CRCW0402220RJNED; Vendor Part Status: ACTIVE; WEIGHT: 0.00065g
R27 R29 R30 R39 = RESISTOR: RESISTOR, THICK FILM, 1k, -5%/+5%, 0.063W, 50V, -55DEGC/+155DEGC, 0402, SMD; AutoDoc File: https://notefied-dynamic-precision.com/DB/Apps/Desktop/Item/Object.aspx?id=114559; BU Name: TEXAS INSTRUMENTS NORWAY; Budget Currency: EUR; Budget Price: 0.014; Client Status: UNDER_REVIEW; Country of Origin: ISRAEL; Datasheet URL 1: http://www.vishay.com/docs/20035/dcrcwe3.pdf; Datasheet URL 2: N/A; Definied Quality: INDUSTRIAL; Esd Level: N/A; Last Time Buy: N/A; Lead Time: 18; LifeCycle Status: ACTIVE; MPN: RESISTOR_0402_1k_+/-5%_50V_0.063W_M_+/-200ppm; MPN Status: ACTIVE; MSL: N/A; MTBF: N/A; MTBF Standard: N/A; Manufacturer: MANUFACTURER SELECTION; Max Oper Temp: +155DEGC; Max TC: +200PPM/DEGC; Max Tol: +5%; Min Oper Temp: -55DEGC; Min TC: -200PPM/DEGC; Min Tol: -5%; Mounting Type: SMD; NOTE Status: PREFERRED; Old Footprint: RESC1005X40N; PCB Package: 0402; Packing Size: 10000; Packing Type: TAPE_&_REEL; Part Number: 01-22486; Part Type: RESISTOR\0402\STANDARD; REACH/SVHC_COMPLIANCE: COMPLIANT; REACH/SVHC_DETAILS: SVHC LIST VERSION Dec 17, 2015; REACH/SVHC_SOURCE: MATERIAL DECLARATION; REACH/SVHC_STATUS: UNAFFECTED; Resistor Type: THICK FILM; Revision: R000; RoHS Status: ROHS_COMPLIANT; Rtd Current: N/A; Rtd Power: 0.063W; Rtd Voltage: 50V; Vendor: VISHAY; Vendor Part Number: CRCW04021K00JNED; Vendor Part Status: ACTIVE; WEIGHT: 0.00065g
R28 = RESISTOR: RESISTOR, THICK FILM, 4.87k, -1%/+1%, 0.063W, 50V, -55DEGC/+155DEGC, 0402, SMD; AutoDoc File: https://notefied-dynamic-precision.com/DB/Apps/Desktop/Item/Object.aspx?id=114567; BU Name: TEXAS INSTRUMENTS NORWAY; Budget Currency: EUR; Budget Price: 0.012; Client Status: UNDER_REVIEW; Country of Origin: ISRAEL; Datasheet URL 1: http://www.vishay.com/docs/20035/dcrcwe3.pdf; Datasheet URL 2: N/A; Definied Quality: INDUSTRIAL; Esd Level: N/A; Last Time Buy: N/A; Lead Time: 14; LifeCycle Status: ACTIVE; MPN: RESISTOR_0402_4.87k_+/-1%_50V_0.063W_M_+/-100ppm; MPN Status: ACTIVE; MSL: N/A; MTBF: N/A; MTBF Standard: N/A; Manufacturer: MANUFACTURER SELECTION; Max Oper Temp: +155DEGC; Max TC: +100PPM/DEGC; Max Tol: +1%; Min Oper Temp: -55DEGC; Min TC: -100PPM/DEGC; Min Tol: -1%; Mounting Type: SMD; NOTE Status: PREFERRED; Old Footprint: RESC1005X40N; PCB Package: 0402; Packing Size: 10000; Packing Type: TAPE_&_REEL; Part Number: 01-22494; Part Type: RESISTOR\0402\PRECISION; REACH/SVHC_COMPLIANCE: COMPLIANT; REACH/SVHC_DETAILS: SVHC LIST VERSION Jun 20, 2016; REACH/SVHC_SOURCE: MATERIAL DECLARATION; REACH/SVHC_STATUS: UNAFFECTED; Resistor Type: THICK FILM; Revision: R000; RoHS Status: ROHS_COMPLIANT_WITH_EXEMPTION; Rtd Current: N/A; Rtd Power: 0.063W; Rtd Voltage: 50V; Vendor: VISHAY; Vendor Part Number: CRCW04024K87FKED; Vendor Part Status: ACTIVE; WEIGHT: 0.00065g
R31 = RESISTOR: RESISTOR, THICK FILM, 51, -5%/+5%, 0.063W, 50V, -55DEGC/+155DEGC, 0402, SMD; AutoDoc File: https://notefied-dynamic-precision.com/DB/Apps/Desktop/Item/Object.aspx?id=114554; BU Name: TEXAS INSTRUMENTS NORWAY; Budget Currency: EUR; Budget Price: 0.014; Client Status: UNDER_REVIEW; Country of Origin: ISRAEL; Datasheet URL 1: http://www.vishay.com/docs/20035/dcrcwe3.pdf; Datasheet URL 2: N/A; Definied Quality: INDUSTRIAL; Esd Level: N/A; Last Time Buy: N/A; Lead Time: 18; LifeCycle Status: ACTIVE; MPN: RESISTOR_0402_51_+/-5%_50V_0.063W_M_+/-200ppm; MPN Status: ACTIVE; MSL: N/A; MTBF: N/A; MTBF Standard: N/A; Manufacturer: MANUFACTURER SELECTION; Max Oper Temp: +155DEGC; Max TC: +200PPM/DEGC; Max Tol: +5%; Min Oper Temp: -55DEGC; Min TC: -200PPM/DEGC; Min Tol: -5%; Mounting Type: SMD; NOTE Status: PREFERRED; Old Footprint: RESC1005X40N; PCB Package: 0402; Packing Size: 10000; Packing Type: TAPE_&_REEL; Part Number: 01-22481; Part Type: RESISTOR\0402\STANDARD; REACH/SVHC_COMPLIANCE: COMPLIANT; REACH/SVHC_DETAILS: SVHC LIST VERSION Jun 20, 2016; REACH/SVHC_SOURCE: MATERIAL DECLARATION; REACH/SVHC_STATUS: UNAFFECTED; Resistor Type: THICK FILM; Revision: R000; RoHS Status: ROHS_COMPLIANT; Rtd Current: N/A; Rtd Power: 0.063W; Rtd Voltage: 50V; Vendor: VISHAY; Vendor Part Number: CRCW040251R0JNED; Vendor Part Status: ACTIVE; WEIGHT: 0.00065g
R32 = RESISTOR: RESISTOR, THICK FILM, 33k, -1%/+1%, 0.063W, 50V, -55DEGC/+155DEGC, 0402, SMD; AutoDoc File: https://notefied-dynamic-precision.com/DB/Apps/Desktop/Item/Object.aspx?id=114550; BU Name: TEXAS INSTRUMENTS NORWAY; Budget Currency: EUR; Budget Price: 0.012; Client Status: UNDER_REVIEW; Country of Origin: ISRAEL; Datasheet URL 1: http://www.vishay.com/docs/20035/dcrcwe3.pdf; Datasheet URL 2: N/A; Definied Quality: INDUSTRIAL; Esd Level: N/A; Last Time Buy: N/A; Lead Time: 14; LifeCycle Status: ACTIVE; MPN: RESISTOR_0402_33k_+/-1%_50V_0.063W_M_+/-100PPM; MPN Status: ACTIVE; MSL: N/A; MTBF: N/A; MTBF Standard: N/A; Manufacturer: MANUFACTURER SELECTION; Max Oper Temp: +155DEGC; Max TC: +100PPM/DEGC; Max Tol: +1%; Min Oper Temp: -55DEGC; Min TC: -100PPM/DEGC; Min Tol: -1%; Mounting Type: SMD; NOTE Status: PREFERRED; Old Footprint: RESC1005X40N; PCB Package: 0402; Packing Size: 10000; Packing Type: TAPE_&_REEL; Part Number: 01-22477; Part Type: RESISTOR\0402\PRECISION; REACH/SVHC_COMPLIANCE: COMPLIANT; REACH/SVHC_DETAILS: SVHC LIST VERSION Jun 20, 2016; REACH/SVHC_SOURCE: MATERIAL DECLARATION; REACH/SVHC_STATUS: UNAFFECTED; Resistor Type: THICK FILM; Revision: R000; RoHS Status: ROHS_COMPLIANT_WITH_EXEMPTION; Rtd Current: N/A; Rtd Power: 0.063W; Rtd Voltage: 50V; Vendor: VISHAY; Vendor Part Number: CRCW040233K0FKED; Vendor Part Status: ACTIVE; WEIGHT: 0.00060916g
R33 = RESISTOR: RESISTOR, THICK FILM, 51k, -5%/+5%, 0.063W, 50V, -55DEGC/+155DEGC, 0402, SMD; AutoDoc File: https://notefied-dynamic-precision.com/DB/Apps/Desktop/Item/Object.aspx?id=114564; BU Name: TEXAS INSTRUMENTS NORWAY; Budget Currency: EUR; Budget Price: 0.014; Client Status: UNDER_REVIEW; Country of Origin: ISRAEL; Datasheet URL 1: http://www.vishay.com/docs/20035/dcrcwe3.pdf; Datasheet URL 2: N/A; Definied Quality: INDUSTRIAL; Esd Level: N/A; Last Time Buy: N/A; Lead Time: 18; LifeCycle Status: ACTIVE; MPN: RESISTOR_0402_51k_+/-5%_50V_0.063W_M_+/-200ppm; MPN Status: ACTIVE; MSL: N/A; MTBF: N/A; MTBF Standard: N/A; Manufacturer: MANUFACTURER SELECTION; Max Oper Temp: +155DEGC; Max TC: +200PPM/DEGC; Max Tol: +5%; Min Oper Temp: -55DEGC; Min TC: -200PPM/DEGC; Min Tol: -5%; Mounting Type: SMD; NOTE Status: PREFERRED; Old Footprint: RESC1005X40N; PCB Package: 0402; Packing Size: 10000; Packing Type: TAPE_&_REEL; Part Number: 01-22491; Part Type: RESISTOR\0402\STANDARD; REACH/SVHC_COMPLIANCE: COMPLIANT; REACH/SVHC_DETAILS: SVHC LIST VERSION Jun 20, 2016; REACH/SVHC_SOURCE: MATERIAL DECLARATION; REACH/SVHC_STATUS: UNAFFECTED; Resistor Type: THICK FILM; Revision: R000; RoHS Status: ROHS_COMPLIANT; Rtd Current: N/A; Rtd Power: 0.063W; Rtd Voltage: 50V; Vendor: VISHAY; Vendor Part Number: CRCW040251K0JNED; Vendor Part Status: ACTIVE; WEIGHT: 0.00065g
R34 = RESISTOR: RESISTOR, THICK FILM, 30k, -5%/+5%, 0.063W, 50V, -55DEGC/+155DEGC, 0402, SMD; AutoDoc File: https://notefied-dynamic-precision.com/DB/Apps/Desktop/Item/Object.aspx?id=114563; BU Name: TEXAS INSTRUMENTS NORWAY; Budget Currency: EUR; Budget Price: 0.014; Client Status: UNDER_REVIEW; Country of Origin: MISSING INFO; Datasheet URL 1: http://www.vishay.com/docs/20035/dcrcwe3.pdf; Datasheet URL 2: N/A; Definied Quality: INDUSTRIAL; Esd Level: N/A; Last Time Buy: N/A; Lead Time: 18; LifeCycle Status: ACTIVE; MPN: RESISTOR_0402_30k_+/-5%_50V_0.063W_M_+/-200ppm; MPN Status: ACTIVE; MSL: N/A; MTBF: N/A; MTBF Standard: N/A; Manufacturer: MANUFACTURER SELECTION; Max Oper Temp: +155DEGC; Max TC: +200PPM/DEGC; Max Tol: +5%; Min Oper Temp: -55DEGC; Min TC: -200PPM/DEGC; Min Tol: -5%; Mounting Type: SMD; NOTE Status: PREFERRED; Old Footprint: RESC1005X40N; PCB Package: 0402; Packing Size: 10000; Packing Type: TAPE_&_REEL; Part Number: 01-22490; Part Type: RESISTOR\0402\STANDARD; REACH/SVHC_COMPLIANCE: COMPLIANT; REACH/SVHC_DETAILS: SVHC LIST VERSION Jun 20, 2016; REACH/SVHC_SOURCE: MATERIAL DECLARATION; REACH/SVHC_STATUS: UNAFFECTED; Resistor Type: THICK FILM; Revision: R000; RoHS Status: ROHS_COMPLIANT; Rtd Current: N/A; Rtd Power: 0.063W; Rtd Voltage: 50V; Vendor: VISHAY; Vendor Part Number: CRCW040230K0JNED; Vendor Part Status: ACTIVE; WEIGHT: 0.00065g
R82 R83 R115 = RESISTOR: RESISTOR, THICK FILM, 10k, -5%/+5%, 0.05W, 30V, -55DEGC/+155DEGC, 0201, SMD; ALT_SYMBOLS: RESC0603X35L,RESC0603X35M; AutoDoc File: https://notefied-dynamic-precision.com/DB/Apps/Desktop/Item/Object.aspx?id=59003; BU Name: DYNAMIC PRECISION GDANSK; Budget Currency: USD; Budget Price: 0.0041; Country of Origin: TAIWAN; Datasheet URL 1: http://www.vishay.com/docs/20052/crcw0201e3.pdf; Datasheet URL 2: N/A; Definied Quality: INDUSTRIAL; Esd Level: N/A; Last Time Buy: N/A; Lead Time: 7; LifeCycle Status: ACTIVE; MPN: RESISTOR_0402_10k_+/-5%_50V_0.063W_M_+/-200ppm; MPN Status: ACTIVE; MSL: N/A; MTBF: N/A; MTBF Standard: N/A; Manufacturer: MANUFACTURER SELECTION; Max Oper Temp: +155DEGC; Max TC: +200PPM/DEGC; Max Tol: +5%; Min Oper Temp: -55DEGC; Min TC: -200PPM/DEGC; Min Tol: -5%; Mounting Type: SMD; NOTE Status: PREFERRED; Old Footprint: RESC1005X40N; PCB Package: 0201; Packing Size: 10000; Packing Type: TAPE_&_REEL; Part Number: 01-04196; Part Type: RESISTOR\0201\STANDARD; REACH/SVHC_COMPLIANCE: COMPLIANT; REACH/SVHC_DETAILS: SVHC LIST VERSION Dec 17, 2015; REACH/SVHC_SOURCE: MATERIAL DECLARATION; REACH/SVHC_STATUS: UNAFFECTED; Resistor Type: THICK FILM; Revision: R001; RoHS Status: ROHS_COMPLIANT; Rtd Current: N/A; Rtd Power: 0.05W; Rtd Voltage: 30V; Vendor: VISHAY; Vendor Part Number: CRCW020110K0JNED; Vendor Part Status: ACTIVE; WEIGHT: 0.00017g
R84 = RESISTOR: RESISTOR, THICK FILM, 12k, -1%/+1%, 0.05W, 30V, -55DEGC/+155DEGC, 0201, SMD; ALT_SYMBOLS: RESC0603X35L,RESC0603X35M; AutoDoc File: https://notefied-dynamic-precision.com/DB/Apps/Desktop/Item/Object.aspx?id=58894; BU Name: DYNAMIC PRECISION GDANSK; Budget Currency: USD; Budget Price: 0.0195; Country of Origin: TAIWAN; Datasheet URL 1: http://www.vishay.com/docs/20052/crcw0201e3.pdf; Datasheet URL 2: N/A; Last Time Buy: N/A; Lead Time: 7; Max Oper Temp: +155DEGC; Max TC: +100PPM/DEGC; Max Tol: +1%; Min Oper Temp: -55DEGC; Min TC: -100PPM/DEGC; Min Tol: -1%; Mounting Type: SMD; PCB Package: 0201; Packing Size: 10000; Packing Type: TAPE_&_REEL; Part Number: 01-04087; Part Type: RESISTOR\0201\PRECISION; Resistor Type: THICK FILM; Revision: R001; RoHS Status: ROHS_COMPLIANT; Rtd Current: N/A; Rtd Power: 0.05W; Rtd Voltage: 30V; Vendor: VISHAY; Vendor Part Number: CRCW020112K0FKED; Vendor Part Status: ACTIVE; Weight: 0.00017g
R85 = RESISTOR: RESISTOR, THICK FILM, 510k, -5%/+5%, 0.063W, 50V, -55DEGC/+155DEGC, 0402, SMD; ALT_SYMBOLS: RESC1005X40L,RESC1005X40M; AutoDoc File: https://notefied-dynamic-precision.com/DB/Apps/Desktop/Item/Object.aspx?id=47169; BU Name: DYNAMIC PRECISION GDANSK; Budget Currency: EUR; Budget Price: 0.014; Country of Origin: MISSING INFO; Datasheet URL 1: http://www.vishay.com/docs/20035/dcrcwe3.pdf; Datasheet URL 2: N/A; Last Time Buy: N/A; Lead Time: 18; Max Oper Temp: +155DEGC; Max TC: +200PPM/DEGC; Max Tol: +5%; Min Oper Temp: -55DEGC; Min TC: -200PPM/DEGC; Min Tol: -5%; Mounting Type: SMD; PCB Package: 0402; Packing Size: 10000; Packing Type: TAPE_&_REEL; Part Number: 01-01285; Part Type: RESISTOR\0402\STANDARD; Resistor Type: THICK FILM; Revision: R001; RoHS Status: ROHS_COMPLIANT; Rtd Current: N/A; Rtd Power: 0.063W; Rtd Voltage: 50V; Vendor: VISHAY; Vendor Part Number: CRCW0402510KJNED; Vendor Part Status: ACTIVE; Weight: 0.00065g
R86 = RESISTOR: RESISTOR, DO NOT MOUNT, 0402, SMD; AutoDoc File: https://notefied-dynamic-precision.com/DB/Apps/Desktop/Item/Object.aspx?id=113312; BU Name: TEXAS INSTRUMENTS NORWAY; Budget Currency: N/A; Budget Price: N/A; Country of Origin: MISSING INFO; Datasheet URL 1: N/A; Datasheet URL 2: N/A; Last Time Buy: N/A; Lead Time: N/A; Max Oper Temp: N/A; Max TC: N/A; Max Tol: N/A; Min Oper Temp: N/A; Min TC: N/A; Min Tol: N/A; Mounting Type: SMD; PCB Package: 0402; Packing Size: N/A; Part Number: 01-22339; Part Type: RESISTOR\0402\STANDARD; Resistance: N/A; Resistor Type: THICK FILM; Revision: R000; RoHS Status: MISSING_INFO; Rtd Current: N/A; Rtd Power: N/A; Rtd Voltage: N/A; Vendor: DO NOT MOUNT; Vendor Part Status: ACTIVE; Weight: N/A
R87 = RESISTOR: RESISTOR, THICK FILM, 1M, -1%/+1%, 0.063W, 50V, -55DEGC/+155DEGC, 0402, SMD; AutoDoc File: https://notefied-dynamic-precision.com/DB/Apps/Desktop/Item/Object.aspx?id=114549; BU Name: TEXAS INSTRUMENTS NORWAY; Budget Currency: EUR; Budget Price: 0.012; Client Status: UNDER_REVIEW; Country of Origin: ISRAEL; Datasheet URL 1: http://www.vishay.com/docs/20035/dcrcwe3.pdf; Datasheet URL 2: N/A; Last Time Buy: N/A; Lead Time: 14; Max Oper Temp: +155DEGC; Max TC: +100PPM/DEGC; Max Tol: +1%; Min Oper Temp: -55DEGC; Min TC: -100PPM/DEGC; Min Tol: -1%; Mounting Type: SMD; PCB Package: 0402; Packing Size: 10000; Packing Type: TAPE_&_REEL; Part Number: 01-22476; Part Type: RESISTOR\0402\PRECISION; Resistance: 1M; Resistor Type: THICK FILM; Revision: R000; RoHS Status: ROHS_COMPLIANT_WITH_EXEMPTION; Rtd Current: N/A; Rtd Power: 0.063W; Rtd Voltage: 50V; Vendor: VISHAY; Vendor Part Number: CRCW04021M00FKED; Vendor Part Status: ACTIVE; Weight: 0.00060916g
R113 R114 = RESISTOR: RESISTOR, THICK FILM, 1k, -5%/+5%, 0.05W, 30V, -55DEGC/+155DEGC, 0201, SMD; ALT_SYMBOLS: RESC0603X35L,RESC0603X35M; AutoDoc File: https://notefied-dynamic-precision.com/DB/Apps/Desktop/Item/Object.aspx?id=58979; BU Name: DYNAMIC PRECISION GDANSK; Budget Currency: USD; Budget Price: 0.0041; Country of Origin: TAIWAN; Datasheet URL 1: http://www.vishay.com/docs/20052/crcw0201e3.pdf; Datasheet URL 2: N/A; Definied Quality: INDUSTRIAL; Esd Level: N/A; Last Time Buy: N/A; Lead Time: 7; LifeCycle Status: ACTIVE; MPN: RESISTOR_0402_1k_+/-5%_50V_0.063W_M_+/-200ppm; MPN Status: ACTIVE; MSL: N/A; MTBF: N/A; MTBF Standard: N/A; Manufacturer: MANUFACTURER SELECTION; Max Oper Temp: +155DEGC; Max TC: +200PPM/DEGC; Max Tol: +5%; Min Oper Temp: -55DEGC; Min TC: -200PPM/DEGC; Min Tol: -5%; Mounting Type: SMD; NOTE Status: PREFERRED; Old Footprint: RESC1005X40N; PCB Package: 0201; Packing Size: 10000; Packing Type: TAPE_&_REEL; Part Number: 01-04172; Part Type: RESISTOR\0201\STANDARD; Resistor Type: THICK FILM; Revision: R001; RoHS Status: ROHS_COMPLIANT; Rtd Current: N/A; Rtd Power: 0.05W; Rtd Voltage: 30V; Vendor: VISHAY; Vendor Part Number: CRCW02011K00JNED; Vendor Part Status: ACTIVE; WEIGHT: 0.00017g
R116 = RESISTOR: RESISTOR, THICK FILM, 20k, -5%/+5%, 0.05W, 30V, -55DEGC/+155DEGC, 0201, SMD; ALT_SYMBOLS: RESC0603X35L,RESC0603X35M; AutoDoc File: https://notefied-dynamic-precision.com/DB/Apps/Desktop/Item/Object.aspx?id=59010; BU Name: DYNAMIC PRECISION GDANSK; Budget Currency: USD; Budget Price: 0.0041; Country of Origin: TAIWAN; Datasheet URL 1: http://www.vishay.com/docs/20052/crcw0201e3.pdf; Datasheet URL 2: N/A; Last Time Buy: N/A; Lead Time: 7; Max Oper Temp: +155DEGC; Max TC: +200PPM/DEGC; Max Tol: +5%; Min Oper Temp: -55DEGC; Min TC: -200PPM/DEGC; Min Tol: -5%; Mounting Type: SMD; PCB Package: 0201; Packing Size: 10000; Packing Type: TAPE_&_REEL; Part Number: 01-04203; Part Type: RESISTOR\0201\STANDARD; Resistor Type: THICK FILM; Revision: R001; RoHS Status: ROHS_COMPLIANT; Rtd Current: N/A; Rtd Power: 0.05W; Rtd Voltage: 30V; Vendor: VISHAY; Vendor Part Number: CRCW020120K0JNED; Vendor Part Status: ACTIVE; Weight: 0.00017g
TP10 TP11 = HOLE_PTH: NON COMPONENT, HOLE 0.6mm, PLATED HOLE; AutoDoc File: https://notefied-dynamic-precision.com/DB/Apps/Desktop/Item/Object.aspx?id=57336; BU Name: DYNAMIC PRECISION GDANSK; Part Number: 19-00057; Part Type: NON_COMPONENT\HOLE\PLATED; Revision: R001
U5 = IC_PROC_TM4C1294NCPDT_TQFP128: IC, MICROPROCESSOR, TIVA C SERIES MICROCONTROLLER, ARM CRTEX-M4, 2.97V TO 3.63V, TQFP128, SMD; ALT_SYMBOLS: QFP40P1600X1600X120-128L,QFP40P1600X1600X120-128M; AutoDoc File: http://notefied-dynamic-precision.com/DB/Apps/Desktop/Item/Object.aspx?id=96468; Budget Currency: USD; Budget Price: 8.47; Datasheet URL 1: N/A; Datasheet URL 2: http://www.ti.com/lit/ds/symlink/tm4c1294ncpdt.pdf; FPLIST: QFP40P1600X1600X120-128N,QFP40P1600X1600X120-128L,QFP40P1600X1600X120-128M; MPN Status: ACTIVE; MSL: 3; Manufacturer: TEXAS INSTRUMENTS; Max Oper Temp: +85DEGC; Min Oper Temp: -40DEGC; Mounting Type: SMD; NOTE Status: PREFERRED; PCB Package: TQFP128; Packing Size: 500; Packing Type: TAPE_&_REEL; Part Number: 18-29511; Part Type: IC\PROCESSOR\TEXAS; Revision: R001; RoHS Status: ROHS_COMPLIANT; Rtd Voltage: 2.97V TO 3.63V
U6 = IC_REF_LM4040_SC70-5: IC, ANALOG, PRECISION MICROPOWER SHUNT VOLTAGE REFERENCE, 2.5V, SC70-5, SMD; ALT_SYMBOLS: SOT65P210X110-5L,SOT65P210X110-5M; AutoDoc File: http://notefied-dynamic-precision.com/DB/Apps/Desktop/Item/Object.aspx?id=96645; Budget Currency: USD; Budget Price: 0.78; Datasheet URL 1: http://www.ti.com/lit/ml/mpds025f/mpds025f.pdf; Datasheet URL 2: http://www.ti.com/lit/ds/symlink/lm4040b25.pdf; Definied Quality: INDUSTRIAL; Esd Level: N/A; FPLIST: SOT65P210X110-5N,SOT65P210X110-5L,SOT65P210X110-5M; Last Time Buy: N/A; Lead Time: 7; MPN: LM4040B25IDCKR; MPN Status: ACTIVE; MSL: 1; Manufacturer: TEXAS INSTRUMENTS; Max Oper Temp: +85DEGC; Min Oper Temp: -40DEGC; Mounting Type: SMD; NOTE Status: PREFERRED; PCB Package: SC70-5; Packing Size: 3000; Packing Type: TAPE_&_REEL; Part Number: 18-29558; Part Type: IC\ANALOG\PM\REFERENCE; Revision: R001; RoHS Status: ROHS_COMPLIANT; Rtd Voltage: 2.5V; WEIGHT: 0.011098173g
U7 = IC_PM_TPS79601_SON8: IC, ANALOG, ULTRALOW-NOISE, HIGH PSRR, FAST, RF, 1A LOW-DROPOUT LINEAR REGULATORS, VIN:2.7V TO 5.5V, VOUT:1.2V TO 5.5V, SON8, SMD; ALT_SYMBOLS: SON65P300X300X100-9AL,SON65P300X300X100-9AM; AutoDoc File: http://notefied-dynamic-precision.com/DB/Apps/Desktop/Item/Object.aspx?id=96546; Budget Currency: USD; Budget Price: 1; Datasheet URL 1: http://www.ti.com/litv/pdf/mpds118j; Datasheet URL 2: http://www.ti.com/lit/ds/symlink/tps79601.pdf; FPLIST: SON65P300X300X100-9AN,SON65P300X300X100-9AL,SON65P300X300X100-9AM; LifeCycle Status: ACTIVE; MPN: TPS79601DRBR; MPN Status: ACTIVE; MSL: 2; Manufacturer: TEXAS INSTRUMENTS; Max Oper Temp: +125DEGC; Min Oper Temp: -40DEGC; Mounting Type: SMD; NOTE Status: PREFERRED; Old Footprint: SON65P300X300X100-9AN; PCB Package: SON8; Packing Size: 3000; Packing Type: TAPE_&_REEL; Part Number: 18-29530; Part Type: IC\ANALOG\PM\REGULATOR; Revision: R001; RoHS Status: ROHS_COMPLIANT; Rtd Voltage: 1.2V TO 5.4V; WEIGHT: 0.024660813g
